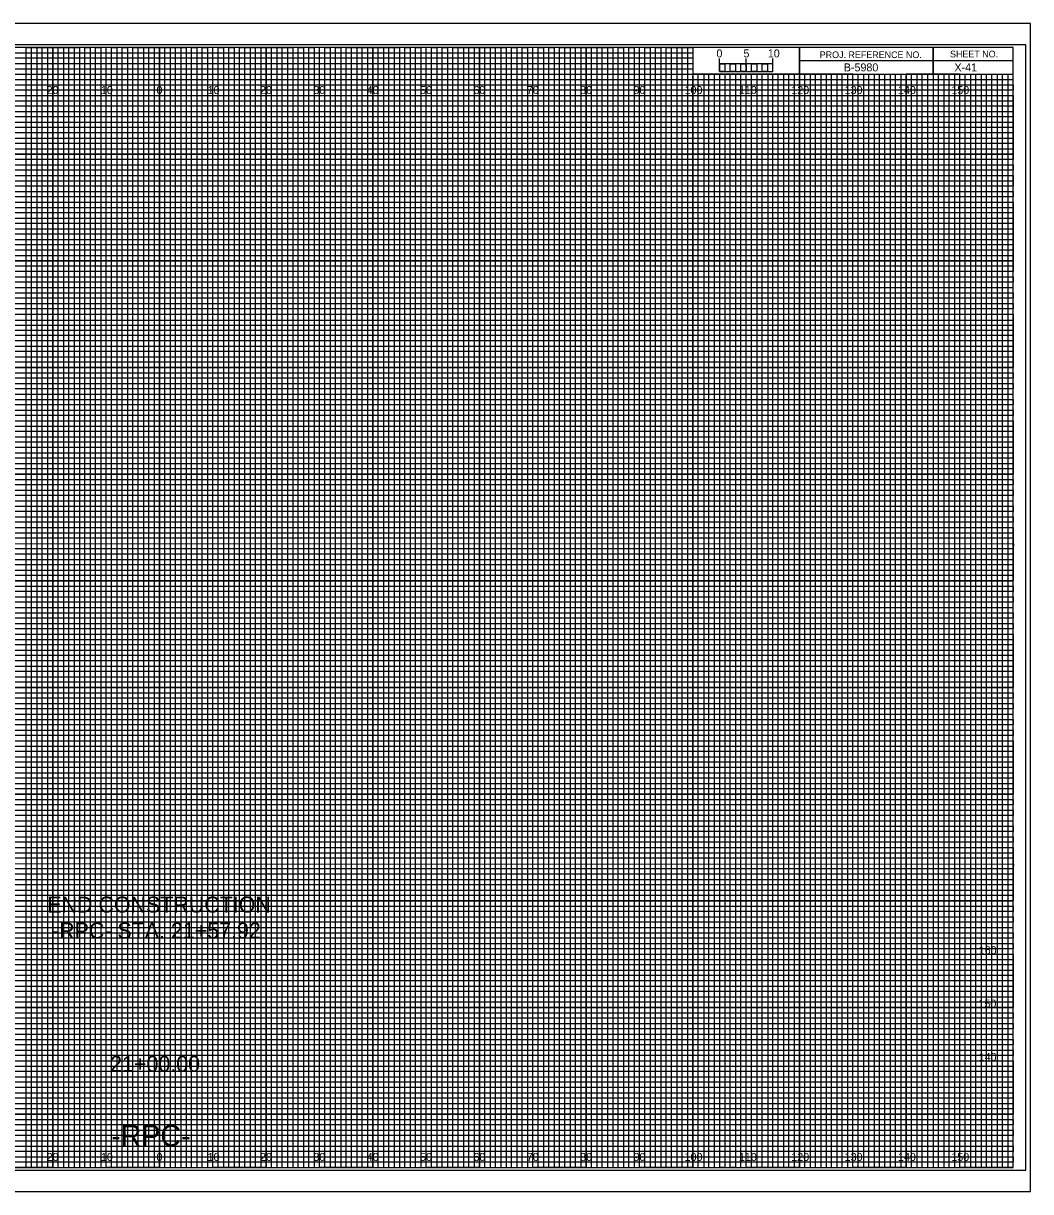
# Model space of a CAD drawing. Extents: x -13 to 323, y -5 to 874.
# Drawn here: x 134.5 to 323.3, y 655.5 to 874.5 of the extents above; entities that cross this region are included whole.
import ezdxf

# ---------------------------------------------------------------- set-up
doc = ezdxf.new("R2010")
doc.units = 0
for name, color, linetype in [('Exist Cross Section Cell', 7, 'Continuous'), ('Exist XS Center Line Elevation Label', 7, 'Continuous'), ('Exist XS Ground Line', 7, 'Continuous'), ('Prop CMT Conc Surface', 7, 'Continuous'), ('Prop CMT Concrete Structures', 7, 'Continuous'), ('Prop CMT Pvmt Course 1', 7, 'Continuous'), ('Prop CMT Pvmt Course 1 CG', 7, 'Continuous'), ('Prop CMT Pvmt Course 2', 7, 'Continuous'), ('Prop CMT Pvmt Course 3', 7, 'Continuous'), ('Prop CMT Pvmt Surface', 7, 'Continuous'), ('Prop CMT Pvmt Surface Shoulder', 7, 'Continuous'), ('Prop CMT Shld Paved Course 1', 7, 'Continuous'), ('Prop CMT Shld Paved Course 2', 7, 'Continuous'), ('Prop CMT Shld Paved Course 3', 7, 'Continuous'), ('Prop CMT Slope Grass', 7, 'Continuous'), ('Prop CMT Subgrade Earthwork', 7, 'Continuous'), ('Scratch_Level_1', 7, 'Continuous')]:
    doc.layers.add(name, color=color, linetype=linetype)

msp = doc.modelspace()

# ---------------------------------------------------------------- linework, layer by layer
at = {"layer": 'Exist XS Center Line Elevation Label'}
for points in [[(125, 660), (135, 660), (135, 870), (145, 870), (145, 660), (155, 660), (155, 870), (165, 870), (165, 660), (175, 660), (175, 870), (185, 870), (185, 660), (195, 660), (195, 870), (205, 870), (205, 660), (215, 660), (215, 870), (225, 870), (225, 660), (235, 660), (235, 870), (245, 870), (245, 660), (255, 660), (255, 870), (259.93, 870), (260, 870), (260, 865), (264.99, 865), (264.99, 660), (275, 660), (275, 865), (285, 865), (285, 660), (295, 660), (295, 865), (305, 865), (305, 660), (315, 660), (315, 865)], [(0, 865), (275, 865)], [(0, 845), (320, 845), (320, 855), (0, 855)], [(0, 825), (320, 825), (320, 835), (0, 835)], [(0, 805), (320, 805), (320, 815), (0, 815)], [(0, 785), (320, 785), (320, 795), (0, 795)], [(0, 765), (320, 765), (320, 775), (0, 775)], [(0, 745), (320, 745), (320, 755), (0, 755)], [(0, 725), (320, 725), (320, 735), (0, 735)], [(0, 705), (320, 705), (320, 715), (0, 715)], [(0, 685), (320, 685), (320, 695), (0, 695)], [(0, 665), (320, 665), (320, 675), (0, 675)]]:
    msp.add_lwpolyline(points, dxfattribs=at)
at = {"layer": 'Exist XS Ground Line'}
for p, q in [((150, 870), (140, 870)), ((140, 870), (140, 660)), ((150, 660), (150, 870)), ((170, 870), (160, 870)), ((160, 870), (160, 660)), ((170, 660), (170, 870)), ((190, 870), (180, 870)), ((180, 870), (180, 660)), ((190, 660), (190, 870)), ((210, 870), (200, 870)), ((200, 870), (200, 660)), ((210, 660), (210, 870)), ((230, 870), (220, 870)), ((220, 870), (220, 660)), ((230, 660), (230, 870)), ((250, 870), (240, 870)), ((240, 870), (240, 660)), ((250, 660), (250, 870)), ((260, 870), (260, 660)), ((270, 660), (270, 865)), ((290, 865), (280, 865)), ((280, 865), (280, 660)), ((290, 660), (290, 865)), ((310, 865), (300, 865)), ((300, 865), (300, 660)), ((310, 660), (310, 865)), ((140, 660), (130, 660)), ((160, 660), (150, 660)), ((180, 660), (170, 660)), ((200, 660), (190, 660)), ((220, 660), (210, 660)), ((240, 660), (230, 660)), ((260, 660), (250, 660)), ((280, 660), (270, 660)), ((300, 660), (290, 660)), ((320, 660), (310, 660)), ((320, 660), (320, 660))]:
    msp.add_line(p, q, dxfattribs=at)
for points in [[(0, 860), (320, 860), (320, 850), (0, 850)], [(0, 840), (320, 840), (320, 830), (0, 830)], [(0, 820), (320, 820), (320, 810), (0, 810)], [(0, 800), (320, 800), (320, 790), (0, 790)], [(0, 780), (320, 780), (320, 770), (0, 770)], [(0, 760), (320, 760), (320, 750), (0, 750)], [(0, 740), (320, 740), (320, 730), (0, 730)], [(0, 720), (320, 720), (320, 710), (0, 710)], [(0, 700), (320, 700), (320, 690), (0, 690)], [(0, 680), (320, 680), (320, 670), (0, 670)]]:
    msp.add_lwpolyline(points, dxfattribs=at)
at = {"layer": 'Prop CMT Pvmt Course 2'}
for p, q in [((265, 865.49), (265, 867.9)), ((265, 866.9), (265, 867.9)), ((270, 865.49), (270, 867.9)), ((275, 865.49), (275, 867.9)), ((275, 866.9), (275, 867.9))]:
    msp.add_line(p, q, dxfattribs=at)
for points in [[(275, 866.9), (265, 866.9), (265, 865.49), (275, 865.49)], [(265, 866.9), (266, 866.9), (266, 865.49), (265, 865.49)], [(267, 866.9), (268, 866.9), (268, 865.49), (267, 865.49)], [(269, 866.9), (270, 866.9), (270, 865.49), (269, 865.49)], [(271, 866.9), (272, 866.9), (272, 865.49), (271, 865.49)], [(273, 866.9), (274, 866.9), (274, 865.49), (273, 865.49)]]:
    msp.add_lwpolyline(points, close=True, dxfattribs=at)
at = {"layer": 'Prop CMT Pvmt Course 3'}
msp.add_lwpolyline([(-13.4, 655.5), (323.3, 655.5), (323.3, 874.5), (-13.4, 874.5)], close=True, dxfattribs=at)
at = {"layer": 'Prop CMT Pvmt Surface'}
for p, q in [((140, 660), (140, 870)), ((150, 660), (150, 870)), ((160, 660), (160, 870)), ((170, 660), (170, 870)), ((180, 660), (180, 870)), ((190, 660), (190, 870)), ((200, 660), (200, 870)), ((210, 660), (210, 870)), ((220, 660), (220, 870)), ((230, 660), (230, 870)), ((240, 660), (240, 870)), ((250, 660), (250, 870)), ((260, 660), (260, 864.69)), ((270, 660), (270, 864.69)), ((280, 660), (280, 864.69)), ((290, 660), (290, 864.69)), ((300, 660), (300, 864.69)), ((310, 660), (310, 864.69)), ((0, 860), (320, 860)), ((0, 850), (320, 850)), ((0, 840), (320, 840)), ((0, 830), (320, 830)), ((0, 820), (320, 820)), ((0, 810), (320, 810)), ((0, 800), (320, 800)), ((0, 790), (320, 790)), ((0, 780), (320, 780)), ((0, 770), (320, 770)), ((0, 760), (320, 760)), ((0, 750), (320, 750)), ((0, 740), (320, 740)), ((0, 730), (320, 730)), ((0, 720), (320, 720)), ((0, 710), (320, 710)), ((0, 700), (320, 700)), ((0, 690), (320, 690)), ((0, 680), (320, 680)), ((0, 670), (320, 670))]:
    msp.add_line(p, q, dxfattribs=at)
at = {"layer": 'Prop CMT Pvmt Surface Shoulder'}
for p, q in [((323.3, 874.5), (-13.4, 874.5)), ((-13.4, 655.5), (323.3, 655.5))]:
    msp.add_line(p, q, dxfattribs=at)
at = {"layer": 'Prop CMT Shld Paved Course 1'}
for p, q in [((0, 869), (260, 869)), ((260, 867.98), (0, 867.98)), ((260, 869), (260, 867.98)), ((0, 867), (260, 867)), ((260, 865.89), (0, 865.89)), ((260, 867), (260, 865.89)), ((0, 864), (320, 864))]:
    msp.add_line(p, q, dxfattribs=at)
for points in [[(0, 863), (270, 863), (320, 863), (320, 862), (0, 862)], [(0, 861), (320, 861), (320, 859), (0, 859)], [(0, 858), (320, 858), (320, 857), (0, 856.98)], [(0, 856), (320, 856), (320, 854), (0, 854)], [(0, 853), (320, 853), (320, 852), (0, 852)], [(0, 851), (320, 851), (320, 849), (0, 849)], [(0, 848), (320, 848), (320, 847), (0, 847)], [(0, 846), (320, 846), (320, 844), (0, 844)], [(0, 843), (320, 843), (320, 842), (0, 842)], [(0, 841), (320, 841), (320, 839), (0, 839)], [(0, 838), (320, 838), (320, 837), (0, 837)], [(0, 836), (320, 836), (320, 833.95), (320, 833), (320, 832), (0, 832)], [(0, 834), (320, 834), (320, 833), (0, 833)], [(0, 831), (320, 831), (320, 829), (0, 829.03)], [(0, 829.03), (320, 829), (320, 828), (0, 828)], [(0, 827), (320, 827), (320, 826), (0, 826)], [(0, 824), (320, 824), (320, 823), (0, 823)], [(0, 822), (320, 822), (320, 821), (0, 821)], [(-0.07, 818.89), (320, 818.89), (320, 817.88), (-0.07, 817.88)], [(0, 817), (320, 817), (320, 816), (0, 816)], [(0, 814), (320, 814), (320, 813), (0, 813)], [(0, 812), (320, 812), (320, 811), (0, 811)], [(0, 809), (320, 809), (320, 808), (0, 808)], [(0, 807), (320, 807), (320, 806), (0, 806)], [(0, 804), (320, 804), (320, 803), (0, 803)], [(0, 802), (320, 802), (320, 801), (0, 801)], [(0, 799), (320, 799), (319.99, 797.98), (0, 798)], [(0, 797), (320, 797), (320, 796), (0, 796)], [(0, 794), (320, 794), (320, 793), (0, 793)], [(0, 792), (320, 792), (320, 791), (0, 791)], [(0, 789), (320, 789), (320, 788), (0, 788)], [(0, 787), (320, 787), (320, 786), (0, 786)], [(0, 784), (320, 784), (320, 783), (0, 783)], [(0, 782), (320, 782), (320, 781), (0, 781)], [(0, 779), (320, 779), (320, 778), (0, 778)], [(0, 776.99), (320.07, 776.91), (320, 776), (0, 776)], [(0, 774), (320, 774), (320, 773), (0, 773)], [(0, 772), (320, 772), (320, 771), (0, 771)], [(0, 769), (320, 769), (320, 768), (0, 768)], [(0, 767), (320, 767), (320, 766), (0, 766)], [(0, 764), (320, 764), (320, 763), (0, 763)], [(0, 762), (320, 762), (320, 761), (0, 761)], [(0, 759), (320, 759), (320, 758), (0, 758)], [(0, 757), (320, 757), (320, 756), (0, 756)], [(0, 754), (320, 754), (320, 753), (0, 753)], [(0, 752), (320, 752), (320, 751), (0, 751)], [(0, 749), (320, 749), (320, 748), (0, 748)], [(0, 747), (320, 747), (320, 746), (0, 746)], [(0, 744), (320, 744), (320, 743), (0, 743)], [(0, 742), (320, 742), (320, 741), (0, 741)], [(0, 739), (320, 739), (319.99, 737.98), (0, 738)], [(0, 737), (320, 737), (320, 736), (0, 736)], [(0, 734), (320, 734), (320, 733), (0, 733)], [(0, 732), (320, 732), (320, 731), (0, 731)], [(0, 729), (320, 729), (320, 728), (0, 728)], [(0, 727), (320, 727), (320, 726), (0, 726)], [(0, 724), (320, 724), (320, 723), (0, 723)], [(0, 722), (320, 722), (320, 721), (0, 721)], [(0, 719), (320, 719), (320, 718), (0, 718)], [(0, 716.99), (320.07, 716.91), (320, 716), (0, 716)], [(0, 714), (320, 714), (320, 713), (0, 713)], [(0, 712), (320, 712), (320, 711), (0, 711)], [(0, 709), (320, 709), (320, 708), (0, 708)], [(0, 707), (320, 707), (320, 706), (0, 706)], [(0, 704), (320, 704), (320, 703), (0, 703)], [(0, 702), (320, 702), (320, 701), (0, 701)], [(0, 699), (320, 699), (320, 698), (0, 698)], [(0, 697), (320, 697), (320, 696), (0, 696)], [(0, 694), (320, 694), (320, 693), (0, 693)], [(0, 692), (320, 692), (320, 691), (0, 691)], [(0, 689), (320, 689), (320, 688), (0, 688)], [(0, 687), (320, 687), (320, 686), (0, 686)], [(0, 684), (320, 684), (320, 683), (0, 683)], [(0, 682), (320, 682), (320, 681), (0, 681)], [(0, 679), (320, 679), (320, 678), (0, 678)], [(0, 677), (320, 677), (320, 676), (0, 676)], [(0, 674), (320, 674), (320, 673), (0, 673)], [(0, 672), (320, 672), (320, 671), (0, 671)], [(0, 669), (320, 669), (320, 668), (0, 668)], [(0, 667), (320, 667), (320, 666), (0, 666)], [(0, 664), (320, 664), (320, 663), (0, 663)], [(0, 662), (320, 662), (320, 661), (0, 661)]]:
    msp.add_lwpolyline(points, dxfattribs=at)
at = {"layer": 'Prop CMT Shld Paved Course 2'}
for p, q in [((305, 870), (305, 865)), ((305, 865), (305, 870)), ((280, 867.5), (280, 865)), ((320, 867.49), (280, 867.49)), ((280, 865), (320, 865))]:
    msp.add_line(p, q, dxfattribs=at)
for points in [[(320, 870), (0, 870), (0, 660), (320, 660)], [(280, 870), (260, 870), (260, 865.03), (280, 865.03)], [(320, 870), (280, 870), (280, 865), (320, 865)]]:
    msp.add_lwpolyline(points, close=True, dxfattribs=at)
at = {"layer": 'Prop CMT Shld Paved Course 3'}
for p, q in [((267, 865), (266.01, 865)), ((266.01, 865), (266.01, 660)), ((267, 660), (267, 865)), ((269, 865), (268, 865)), ((268, 865), (268, 660)), ((269, 660), (269, 865)), ((266.01, 660), (265, 660)), ((268, 660), (267, 660))]:
    msp.add_line(p, q, dxfattribs=at)
for points in [[(135, 660), (136, 660), (136, 870), (137, 870), (137, 660)], [(137, 660), (138, 660), (138, 870), (139, 870), (139, 660)], [(140, 660), (141, 660), (141, 870), (142, 870), (142, 660)], [(142, 660), (143, 660), (143, 870), (144, 870), (144, 660)], [(145, 660), (146, 660), (146, 870), (147, 870), (147, 660)], [(147, 660), (148, 660), (148, 870), (149, 870), (149, 660)], [(150, 660), (151, 660), (151, 870), (152, 870), (152, 660)], [(152, 660), (153, 660), (153, 870), (154, 870), (154, 660)], [(155, 660), (156, 660), (156, 870), (157, 870), (157, 660)], [(157, 660), (158, 660), (158, 870), (159, 870), (159, 660)], [(160, 660), (161, 660), (161, 870), (162, 870), (162, 660)], [(162, 660), (163, 660), (163, 870), (164, 870), (164, 660)], [(165, 660), (166, 660), (166, 870), (167, 870), (167, 660)], [(167, 660), (168, 660), (168, 870), (169, 870), (169, 660)], [(170, 660), (171, 660), (171, 870), (172, 870), (172, 660)], [(172, 660), (173, 660), (173, 870), (174, 870), (174, 660)], [(175, 660), (176, 660), (176, 870), (177, 870), (177, 660)], [(177, 660), (178, 660), (178, 870), (179, 870), (179, 660)], [(180, 660), (181, 660), (181, 870), (182, 870), (182, 660)], [(182, 660), (183, 660), (183, 870), (184, 870), (184, 660)], [(185, 660), (186, 660), (186, 870), (187, 870), (187, 660)], [(187, 660), (188, 660), (188, 870), (189, 870), (189, 660)], [(190, 660), (191, 660), (191, 870), (192, 870), (192, 660)], [(192, 660), (193, 660), (193, 870), (194, 870), (194, 660)], [(195, 660), (196, 660), (196, 870), (197, 870), (197, 660)], [(197, 660), (198, 660), (198, 870), (199, 870), (199, 660)], [(200, 660), (201, 660), (201, 870), (202, 870), (202, 660)], [(202, 660), (203, 660), (203, 870), (204, 870), (204, 660)], [(205, 660), (206, 660), (206, 870), (207, 870), (207, 660)], [(207, 660), (208, 660), (208, 870), (209, 870), (209, 660)], [(210, 660), (211, 660), (211, 870), (212, 870), (212, 660)], [(212, 660), (213, 660), (213, 870), (214, 870), (214, 660)], [(215, 660), (216, 660), (216, 870), (217, 870), (217, 660)], [(217, 660), (218, 660), (218, 870), (219, 870), (219, 660)], [(220, 660), (221, 660), (221, 870), (222, 870), (222, 660)], [(222, 660), (223, 660), (223, 870), (224, 870), (224, 660)], [(225, 660), (226, 660), (226, 870), (227, 870), (227, 660)], [(227, 660), (228, 660), (228, 870), (229, 870), (229, 660)], [(230, 660), (231, 660), (231, 870), (232, 870), (232, 660)], [(232, 660), (233, 660), (233, 870), (234, 870), (234, 660)], [(235, 660), (236, 660), (236, 870), (237, 870), (237, 660)], [(237, 660), (238, 660), (238, 870), (239, 870), (239, 660)], [(240, 660), (241, 660), (241, 870), (242, 870), (242, 660)], [(242, 660), (243, 660), (243, 870), (244, 870), (244, 660)], [(245, 660), (246, 660), (246, 870), (247, 870), (247, 660)], [(247, 660), (248, 660), (248, 870), (249, 870), (249, 660)], [(250, 660), (251, 660), (251, 870), (252, 870), (252, 660)], [(252, 660), (253, 660), (253, 870), (254, 870), (254, 660)], [(255, 660), (256, 660), (256, 870), (257, 870), (257, 660)], [(257, 660), (258, 660), (258, 870), (259, 870), (259, 660)], [(260, 660), (261, 660), (261, 865), (262.02, 865), (262.02, 660)], [(262, 660), (263, 660), (263, 865), (263.99, 865), (263.99, 660)], [(270, 660), (270.98, 660), (270.98, 865), (272, 865), (272, 660)], [(272, 660), (273, 660), (273, 865), (274.05, 865), (274.05, 660)], [(275, 660), (276, 660), (276, 865), (277, 865), (277, 660)], [(277, 660), (278, 660), (278, 865), (279, 865), (279, 660)], [(280, 660), (281, 660), (281, 865), (282, 865), (282, 660)], [(282, 660), (283, 660), (283, 865), (284, 865), (284, 660)], [(285, 660), (286, 660), (286, 865), (287, 865), (287, 660)], [(287, 660), (288, 660), (288, 865), (289, 865), (289, 660)], [(290, 660), (291, 660), (291, 865), (292, 865), (292, 660)], [(292, 660), (293, 660), (293, 865), (294, 865), (294, 660)], [(295, 660), (296, 660), (296, 865), (297, 865), (297, 660)], [(297, 660), (298, 660), (298, 865), (299, 865), (299, 660)], [(300, 660), (301, 660), (301, 865), (302, 865), (302, 660)], [(302, 660), (303, 660), (303, 865), (304, 865), (304, 660)], [(305, 660), (306, 660), (306, 865), (307, 865), (307, 660)], [(307, 660), (308, 660), (308, 865), (309, 865), (309, 660)], [(310, 660), (311, 660), (311, 865), (312, 865), (312, 660)], [(312, 660), (313, 660), (313, 865), (314, 865), (314, 660)], [(315, 660), (316, 660), (316, 865), (317, 865), (317, 660)], [(317, 660), (318, 660), (318, 865), (319, 865), (319, 660)]]:
    msp.add_lwpolyline(points, dxfattribs=at)
at = {"layer": 'Prop CMT Subgrade Earthwork'}
msp.add_lwpolyline([(-10.8, 659.5), (322.4, 659.5), (322.4, 870.5), (-10.8, 870.5)], close=True, dxfattribs=at)

# ---------------------------------------------------------------- texts
at = {"layer": 'Exist Cross Section Cell'}
for s, p in [('20', (138.86, 861.25)), ('10', (149.04, 861.25)), ('0', (159.45, 861.25)), ('0', (159.45, 861.25)), ('10', (169.04, 861.25)), ('20', (178.86, 861.25)), ('30', (188.86, 861.25)), ('40', (198.86, 861.25)), ('50', (208.86, 861.25)), ('60', (218.86, 861.25)), ('70', (228.86, 861.25)), ('80', (238.86, 861.25)), ('90', (248.86, 861.25)), ('100', (258.44, 861.25)), ('110', (268.62, 861.25)), ('120', (278.44, 861.25)), ('130', (288.44, 861.25)), ('140', (298.44, 861.25)), ('150', (308.44, 861.25)), ('20', (138.86, 661.25)), ('10', (149.04, 661.25)), ('0', (159.45, 661.25)), ('0', (159.45, 661.25)), ('10', (169.04, 661.25)), ('20', (178.86, 661.25)), ('30', (188.86, 661.25)), ('40', (198.86, 661.25)), ('50', (208.86, 661.25)), ('60', (218.86, 661.25)), ('70', (228.86, 661.25)), ('80', (238.86, 661.25)), ('90', (248.86, 661.25)), ('100', (258.44, 661.25)), ('110', (268.62, 661.25)), ('120', (278.44, 661.25)), ('130', (288.44, 661.25)), ('140', (298.44, 661.25)), ('150', (308.44, 661.25))]:
    msp.add_text(s, height=1.5, dxfattribs=at).set_placement(p)
at = {"layer": 'Prop CMT Conc Surface'}
for s, p in [('5', (269.47, 868.12)), ('10', (274.04, 868.12))]:
    msp.add_text(s, height=1.5, dxfattribs=at).set_placement(p)
at = {"layer": 'Prop CMT Concrete Structures'}
msp.add_text('B-5980', height=1.5, dxfattribs=at).set_placement((288.28, 865.5))
at = {"layer": 'Prop CMT Pvmt Course 1'}
for s, p in [('160', (313.57, 700)), ('150', (313.52, 690)), ('140', (313.57, 680))]:
    msp.add_text(s, height=1.5, dxfattribs=at).set_placement(p)
at = {"layer": 'Prop CMT Pvmt Course 1 CG'}
msp.add_text('-RPC-', height=4, dxfattribs=at).set_placement((150.97, 664))
at = {"layer": 'Prop CMT Pvmt Course 2'}
msp.add_text('0', height=1.5, dxfattribs=at).set_placement((264.41, 868.12))
at = {"layer": 'Prop CMT Shld Paved Course 2'}
for s, p in [('PROJ. REFERENCE NO.', (283.77, 867.99)), ('SHEET NO.', (308.19, 868.12))]:
    msp.add_text(s, height=1.25, dxfattribs=at).set_placement(p)
at = {"layer": 'Prop CMT Slope Grass'}
for s, p in [('END CONSTRUCTION', (138.99, 707.81)), ('-RPC- STA. 21+57.92', (139.87, 702.94)), ('21+00.00', (150.77, 677.95))]:
    msp.add_text(s, height=3, dxfattribs=at).set_placement(p)
at = {"layer": 'Scratch_Level_1'}
msp.add_text('X-41', height=1.5, dxfattribs=at).set_placement((309.02, 865.5))

doc.saveas('drawing.dxf')
